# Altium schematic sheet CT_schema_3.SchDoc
size 284 x 147 mm
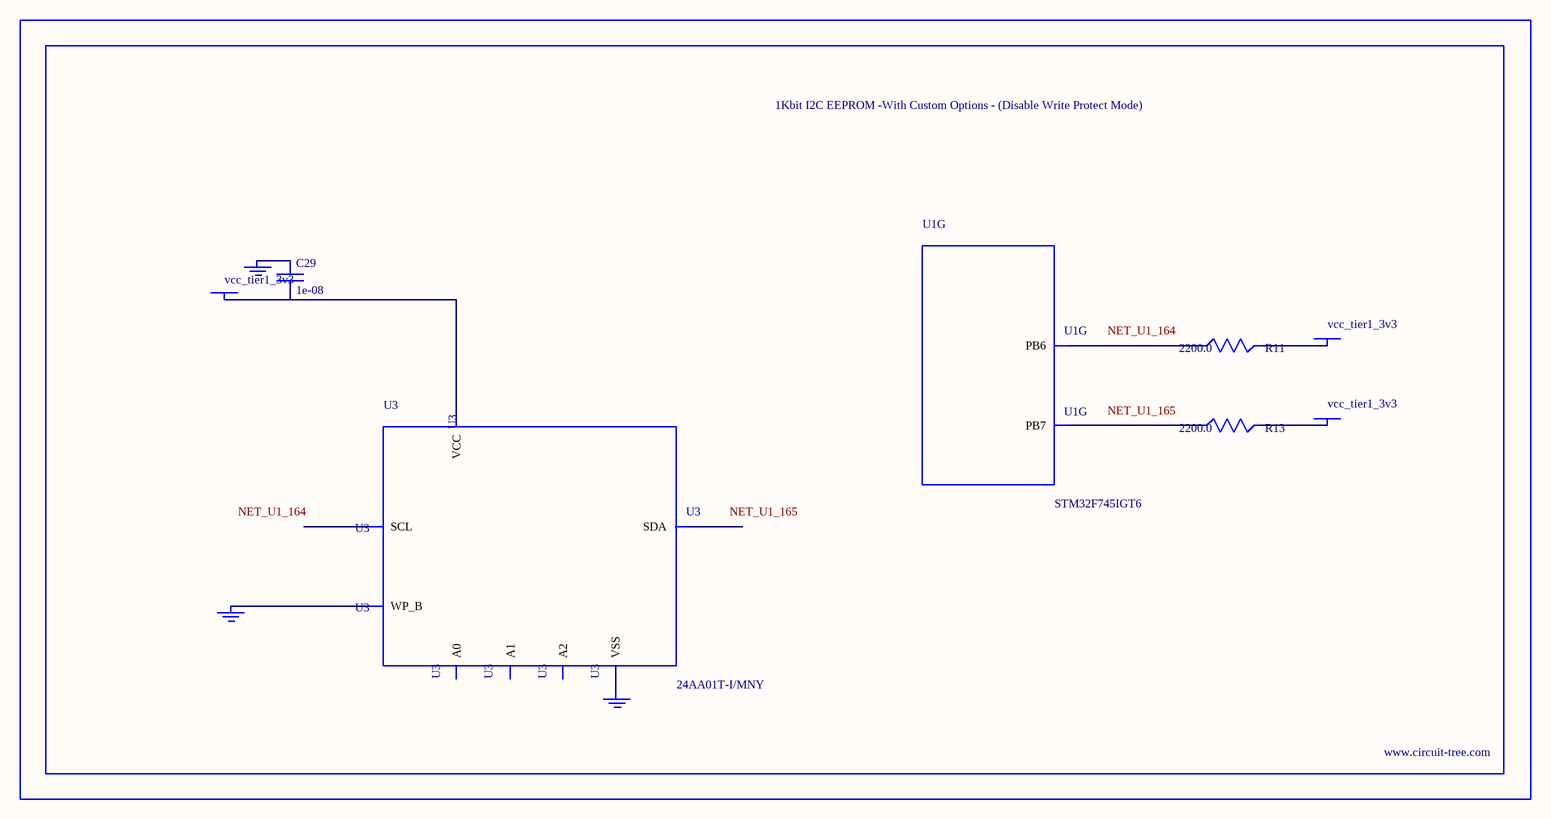
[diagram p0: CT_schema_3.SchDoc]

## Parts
BORDER2  (no value)
C29  1e-08  [C0402]
GND_INSTANCE_2_0  (no value)
GND_INSTANCE_2_1  (no value)
GND_INSTANCE_2_2  (no value)
POWER_INSTANCE_2_0  vcc_tier1_3v3
POWER_INSTANCE_2_1  vcc_tier1_3v3
POWER_INSTANCE_2_2  vcc_tier1_3v3
R11  2200.0  [R0603]
R13  2200.0  [R0603]
U1  STM32F745IGT6  [LQFP176]  (part G of 12)
U3  24AA01T-I/MNY  [TDFN-8/6MM]

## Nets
NetC29_1: C29.1 GND_INSTANCE_2_1.0(GND)
NetC29_2: C29.2 POWER_INSTANCE_2_0.0(PWR) U3.8(VCC)
NetGND_INSTANCE_2_0_0: GND_INSTANCE_2_0.0(GND) U3.7(WP_B)
NetGND_INSTANCE_2_2_0: GND_INSTANCE_2_2.0(GND) U3.4(VSS)
NetPOWER_INSTANCE_2_1_0: POWER_INSTANCE_2_1.0(PWR) R11.2
NetPOWER_INSTANCE_2_2_0: POWER_INSTANCE_2_2.0(PWR) R13.2
NetR11_1: R11.1 U1.164(PB6)
NetR13_1: R13.1 U1.165(PB7)

Not connected (* = marked no-connect by the designer): U3 1(A0) 2(A1) 3(A2) 5(SDA) 6(SCL)

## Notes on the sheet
- Labels drawn without touching a wire or pin: NET_U1_164, NET_U1_165

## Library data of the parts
BORDER2 = BORDER_PAGE2
C29 = C0402C103K3RAC
GND_INSTANCE_2_0-GND_INSTANCE_2_2 = GND
POWER_INSTANCE_2_0-POWER_INSTANCE_2_2 = PWR
R11 R13 = RC0603JR-072K2L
